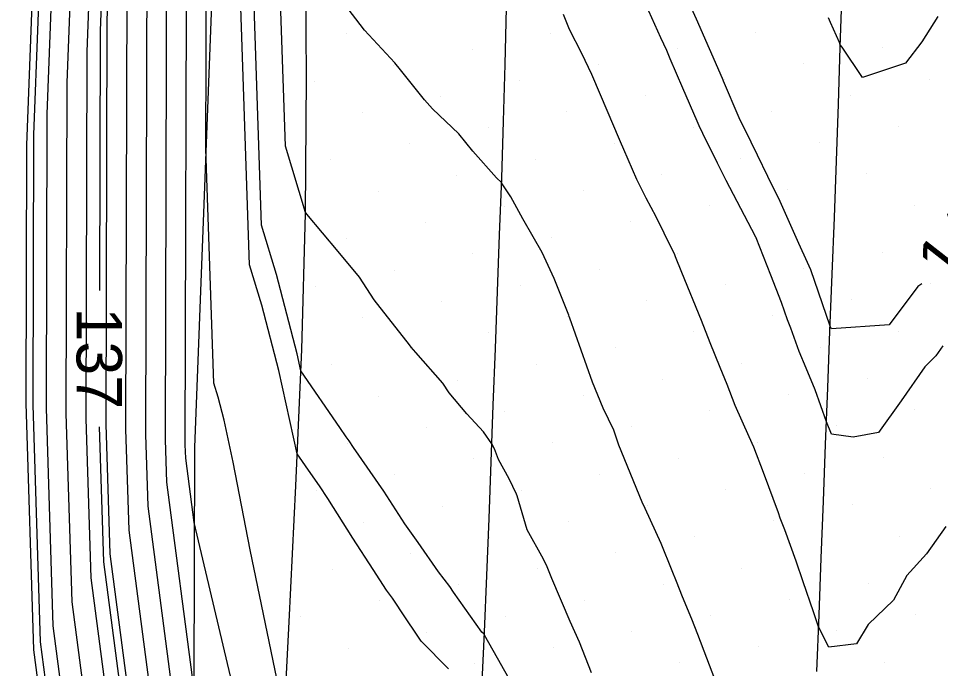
# Model space of a CAD drawing. Extents: x 2354170 to 2357230, y 866100 to 868290.
# Drawn here: x 2355317.68 to 2355358.24, y 866762.57 to 866791.19 of the extents above; entities that cross this region are included whole.
import ezdxf

# ---------------------------------------------------------------- set-up
doc = ezdxf.new("R2010")
doc.units = 0
for name, color, linetype in [('Default', 7, 'Continuous'), ('DTM Contours Major', 7, 'Continuous'), ('DTM Contours Minor', 7, 'Continuous'), ('DTM Contours Minor Text', 7, 'Continuous'), ('Exist DTM Breakline', 7, 'Continuous'), ('Exist DTM Scan Elevation Point', 7, 'Continuous'), ('Exist Roads EOP', 7, 'Continuous'), ('PH Exist DTM Breakline', 7, 'Continuous')]:
    doc.layers.add(name, color=color, linetype=linetype)

msp = doc.modelspace()

# ---------------------------------------------------------------- linework, layer by layer
at = {"layer": 'Default'}
for points in [[(2355319.839, 866834.891), (2355319.852, 866834.326), (2355319.913, 866832.709), (2355319.915, 866832.669), (2355320.627, 866818.532), (2355321.726, 866802.686), (2355321.904, 866800.122), (2355321.563, 866791.1), (2355321.517, 866773.337), (2355321.694, 866767.616), (2355323.737, 866752.092), (2355322.982, 866741.477), (2355322.473, 866736.715), (2355322.653, 866735.162)], [(2355319.531, 866703.142), (2355319.421, 866706.742), (2355319.627, 866715.191), (2355319.642, 866715.296), (2355317.686, 866732.184), (2355319.197, 866746.316), (2355319.69, 866753.255), (2355318.354, 866763.403), (2355318.019, 866774.259), (2355318.049, 866785.607), (2355318.635, 866801.132), (2355318.526, 866802.706), (2355318.518, 866802.818)], [(2355319.453, 866800.879), (2355318.927, 866786.98), (2355318.894, 866774.029), (2355319.189, 866764.456), (2355320.702, 866752.964), (2355320.143, 866745.106), (2355318.882, 866733.317), (2355321.17, 866713.572)], [(2355320.27, 866800.627), (2355319.806, 866788.354), (2355319.768, 866773.798), (2355320.024, 866765.509), (2355321.713, 866752.673), (2355321.089, 866743.896), (2355320.079, 866734.449), (2355322.698, 866711.847)], [(2355321.087, 866800.374), (2355320.685, 866789.727), (2355320.642, 866773.568), (2355320.859, 866766.563), (2355322.725, 866752.382), (2355322.036, 866742.687), (2355321.276, 866735.582), (2355323.508, 866716.313)], [(2355329.376, 866760.508), (2355327.865, 866767.792), (2355327.128, 866771.661), (2355326.722, 866773.501), (2355326.461, 866774.513), (2355326.27, 866775.141), (2355325.924, 866785.443), (2355325.957, 866797.966)], [(2355328.275, 866756.834), (2355325.406, 866768.995), (2355325.033, 866771.829), (2355325.015, 866772.415), (2355325.078, 866796.593)], [(2355336.586, 866762.561), (2355335.385, 866763.78), (2355335.183, 866764.08), (2355334.7, 866764.799), (2355334.129, 866765.669), (2355333.867, 866766.018), (2355333.28, 866766.93), (2355332.387, 866768.311), (2355331.283, 866770.057), (2355330.915, 866770.617), (2355330.533, 866771.155), (2355329.94, 866772.019), (2355329.131, 866775.693), (2355328.387, 866778.567), (2355327.846, 866780.351), (2355327.304, 866796.482)], [(2355325.388, 866761.737), (2355324.198, 866770.776), (2355324.14, 866772.646), (2355324.199, 866795.22)], [(2355323.321, 866793.847), (2355323.266, 866772.876), (2355323.363, 866769.722), (2355325.369, 866754.479), (2355325.841, 866752.48), (2355325.898, 866751.775), (2355325.98, 866750.685), (2355324.941, 866739.991), (2355324.875, 866739.057), (2355324.866, 866738.98), (2355324.891, 866738.771), (2355325.06, 866737.82), (2355327.395, 866727.737), (2355327.467, 866727.872), (2355328.608, 866726.353), (2355329.081, 866725.537), (2355330.039, 866723.985), (2355331.124, 866722.2)], [(2355357.408, 866779.505), (2355357.232, 866779.394), (2355355.983, 866777.697), (2355353.441, 866777.532), (2355353.379, 866777.638), (2355352.535, 866780.118), (2355352.389, 866780.447), (2355352.005, 866781.286), (2355351.185, 866783.131), (2355350.633, 866784.234), (2355350.187, 866785.176), (2355349.913, 866785.74), (2355349.374, 866786.814), (2355348.694, 866788.427), (2355348.673, 866788.476), (2355348.642, 866788.549), (2355347.5, 866791.154), (2355346.762, 866792.79)], [(2355322.442, 866792.473), (2355322.391, 866773.107), (2355322.528, 866768.669), (2355324.748, 866751.801), (2355323.928, 866740.267), (2355323.67, 866737.848), (2355324.43, 866731.285), (2355326.327, 866720.655)], [(2355348.472, 866761.682), (2355347.565, 866764.066), (2355347.299, 866764.743), (2355346.88, 866765.734), (2355346.616, 866766.408), (2355346.425, 866766.874), (2355345.942, 866768.075), (2355345.244, 866769.62), (2355345.117, 866769.897), (2355344.091, 866772.408), (2355343.872, 866773.065), (2355343.401, 866774.03), (2355342.928, 866775.182), (2355341.928, 866778.003), (2355341.898, 866778.075), (2355341.88, 866778.128), (2355341.245, 866779.747), (2355340.707, 866780.887), (2355340.321, 866781.576), (2355339.863, 866782.366), (2355339.332, 866783.339), (2355338.958, 866783.913), (2355338.929, 866783.962), (2355338.71, 866784.177), (2355337.664, 866785.349), (2355337.05, 866786.108), (2355335.895, 866787.206), (2355335.533, 866787.603), (2355334.481, 866788.925), (2355334.236, 866789.229), (2355332.895, 866790.674), (2355332.522, 866791.169), (2355331.742, 866792.195)], [(2355342.884, 866762.382), (2355342.359, 866763.737), (2355341.95, 866764.642), (2355341.134, 866766.537), (2355340.929, 866767.054), (2355340.773, 866767.394), (2355340.047, 866768.678), (2355339.615, 866770.173), (2355339.588, 866770.254), (2355339.261, 866770.922), (2355338.794, 866771.773), (2355338.624, 866772.238), (2355338.498, 866772.468), (2355338.134, 866773), (2355337.405, 866773.784), (2355336.621, 866774.711), (2355336.338, 866775.139), (2355335.156, 866776.488), (2355334.953, 866776.721), (2355334.873, 866776.823), (2355333.329, 866778.797), (2355332.676, 866779.805), (2355331.745, 866780.934), (2355330.36, 866782.577), (2355330.329, 866782.617), (2355330.317, 866782.631), (2355330.307, 866782.641), (2355329.422, 866785.562), (2355329.222, 866791.515)], [(2355358.474, 866768.823), (2355357.615, 866767.624), (2355356.751, 866766.668), (2355356.168, 866765.583), (2355355.047, 866764.517), (2355354.544, 866763.66), (2355353.319, 866763.517), (2355352.873, 866764.411), (2355352.727, 866764.851), (2355352.645, 866765.069), (2355352.187, 866766.395), (2355351.886, 866767.298), (2355351.388, 866768.686), (2355351.187, 866769.199), (2355351.115, 866769.433), (2355350.451, 866771.198), (2355350.022, 866772.311), (2355349.824, 866772.779), (2355349.208, 866774.152), (2355348.855, 866775.078), (2355348.537, 866775.819), (2355348.101, 866776.916), (2355347.718, 866777.891), (2355346.853, 866780.005), (2355346.575, 866780.693), (2355346.532, 866780.823), (2355346.435, 866781.016), (2355345.721, 866782.462), (2355345.289, 866783.281), (2355344.877, 866784.094), (2355344.301, 866785.426), (2355344.159, 866785.752), (2355344.065, 866785.962), (2355343.617, 866787.035), (2355342.891, 866788.718), (2355342.456, 866789.643), (2355341.914, 866790.707), (2355341.648, 866791.37)], [(2355358.116, 866791.273), (2355357.413, 866790.165), (2355356.69, 866789.219), (2355354.798, 866788.593), (2355353.915, 866789.921), (2355353.828, 866790.031), (2355353.787, 866790.127), (2355353.401, 866791.012), (2355353.304, 866791.223)]]:
    msp.add_lwpolyline(points, dxfattribs=at)
at = {"layer": 'DTM Contours Major'}
msp.add_lwpolyline([(2355358.334, 866776.78), (2355358.027, 866776.344), (2355357.548, 866775.85), (2355356.507, 866774.352), (2355355.504, 866772.962), (2355354.392, 866772.754), (2355353.436, 866772.89), (2355353.215, 866773.435), (2355352.723, 866774.836), (2355352.329, 866775.799), (2355352.019, 866776.528), (2355351.654, 866777.563), (2355351.507, 866777.921), (2355351.243, 866778.687), (2355350.772, 866779.883), (2355350.128, 866781.533), (2355350.118, 866781.554), (2355350.099, 866781.589), (2355348.804, 866784.063), (2355348.419, 866784.816), (2355347.785, 866786.118), (2355347.615, 866786.456), (2355347.527, 866786.664), (2355346.907, 866788.116), (2355346.348, 866789.413), (2355346.204, 866789.777), (2355345.939, 866790.337), (2355345.138, 866792.114)], dxfattribs=at)
at = {"layer": 'DTM Contours Minor'}
for points in [[(2355315.242, 866979.053), (2355315.645, 866971.554), (2355315.647, 866971.365), (2355315.697, 866970.436), (2355315.938, 866949.586), (2355316.345, 866939.655), (2355316.229, 866921.7), (2355316.288, 866920.303), (2355316.905, 866909.69), (2355317.696, 866891.211), (2355317.712, 866890.948), (2355317.95, 866878.41), (2355318.776, 866863.441), (2355318.797, 866862.168), (2355319.282, 866848.671), (2355319.596, 866834.276), (2355319.655, 866832.712), (2355319.657, 866832.671), (2355320.396, 866818.024), (2355321.46, 866802.688), (2355321.632, 866800.206), (2355321.27, 866790.642), (2355321.241, 866779.218)], [(2355314.895, 866894.262), (2355315.108, 866889.287), (2355315.119, 866889.115), (2355315.275, 866880.887), (2355316.318, 866861.986), (2355316.331, 866861.214), (2355316.625, 866853.034), (2355317.045, 866833.773), (2355317.084, 866832.738), (2355317.087, 866832.683), (2355318.083, 866812.944), (2355318.793, 866802.704), (2355318.908, 866801.047), (2355318.342, 866786.065), (2355318.311, 866774.182), (2355318.633, 866763.754), (2355320.027, 866753.158), (2355319.512, 866745.912), (2355318.085, 866732.561), (2355320.151, 866714.721), (2355320.138, 866714.631), (2355319.962, 866707.392), (2355320.351, 866694.691)], [(2355325.388, 866761.737), (2355324.198, 866770.776), (2355324.14, 866772.646), (2355324.199, 866795.22)], [(2355339.638, 866761.441), (2355338.172, 866764.043), (2355338.152, 866764.096), (2355338.066, 866764.177), (2355336.81, 866765.934), (2355336.647, 866766.182), (2355336.16, 866766.831), (2355335.256, 866768.116), (2355334.673, 866768.947), (2355333.756, 866770.38), (2355332.42, 866772.302), (2355332.22, 866772.59), (2355332.089, 866772.775), (2355331.811, 866773.177), (2355330.099, 866775.671), (2355329.933, 866776.424), (2355329.029, 866779.919), (2355328.372, 866782.088), (2355327.943, 866794.826)], [(2355321.231, 866773.218), (2355321.415, 866767.265), (2355323.399, 866752.188), (2355322.667, 866741.88), (2355322.074, 866736.337), (2355323.816, 866721.304)]]:
    msp.add_lwpolyline(points, dxfattribs=at)
at = {"layer": 'Exist DTM Breakline'}
for points in [[(2355352.791, 866762.441), (2355352.895, 866764.939), (2355352.989, 866767.437), (2355353.083, 866769.936), (2355353.177, 866772.434), (2355353.272, 866774.932), (2355353.371, 866777.43), (2355353.471, 866779.928), (2355353.57, 866782.426), (2355353.667, 866784.924), (2355353.746, 866787.423), (2355353.825, 866789.922), (2355353.903, 866792.42)], [(2355338.065, 866761.68), (2355338.178, 866764.177), (2355338.282, 866766.675), (2355338.375, 866769.173), (2355338.468, 866771.671), (2355338.562, 866774.17), (2355338.655, 866776.668), (2355338.749, 866779.166), (2355338.843, 866781.664), (2355338.937, 866784.163), (2355339.016, 866786.661), (2355339.079, 866789.16), (2355339.143, 866791.66)]]:
    msp.add_lwpolyline(points, dxfattribs=at)
at = {"layer": 'Exist DTM Scan Elevation Point'}
for p, q in [((2355332.086, 866790.509), (2355332.086, 866790.509)), ((2355341.099, 866790.541), (2355341.099, 866790.541)), ((2355350.113, 866790.573), (2355350.113, 866790.573)), ((2355355.663, 866789.899), (2355355.663, 866789.899)), ((2355337.635, 866789.836), (2355337.635, 866789.836)), ((2355346.649, 866789.867), (2355346.649, 866789.867)), ((2355334.171, 866789.13), (2355334.171, 866789.13)), ((2355343.184, 866789.162), (2355343.184, 866789.162)), ((2355352.198, 866789.193), (2355352.198, 866789.193)), ((2355330.706, 866788.424), (2355330.706, 866788.424)), ((2355339.72, 866788.456), (2355339.72, 866788.456)), ((2355348.734, 866788.488), (2355348.734, 866788.488)), ((2355357.748, 866788.52), (2355357.748, 866788.52)), ((2355336.256, 866787.751), (2355336.256, 866787.751)), ((2355345.269, 866787.782), (2355345.269, 866787.782)), ((2355354.283, 866787.814), (2355354.283, 866787.814)), ((2355341.805, 866787.077), (2355341.805, 866787.077)), ((2355350.819, 866787.108), (2355350.819, 866787.108)), ((2355332.791, 866787.045), (2355332.791, 866787.045)), ((2355338.34, 866786.371), (2355338.34, 866786.371)), ((2355347.354, 866786.403), (2355347.354, 866786.403)), ((2355356.368, 866786.435), (2355356.368, 866786.435)), ((2355334.876, 866785.666), (2355334.876, 866785.666)), ((2355343.89, 866785.697), (2355343.89, 866785.697)), ((2355352.904, 866785.729), (2355352.904, 866785.729)), ((2355349.439, 866785.023), (2355349.439, 866785.023)), ((2355331.412, 866784.96), (2355331.412, 866784.96)), ((2355340.425, 866784.992), (2355340.425, 866784.992)), ((2355336.961, 866784.286), (2355336.961, 866784.286)), ((2355345.975, 866784.318), (2355345.975, 866784.318)), ((2355354.989, 866784.35), (2355354.989, 866784.35)), ((2355333.497, 866783.581), (2355333.497, 866783.581)), ((2355342.51, 866783.612), (2355342.51, 866783.612)), ((2355351.524, 866783.644), (2355351.524, 866783.644)), ((2355339.046, 866782.907), (2355339.046, 866782.907)), ((2355348.06, 866782.938), (2355348.06, 866782.938)), ((2355357.074, 866782.97), (2355357.074, 866782.97)), ((2355335.582, 866782.201), (2355335.582, 866782.201)), ((2355344.595, 866782.233), (2355344.595, 866782.233)), ((2355332.117, 866781.496), (2355332.117, 866781.496)), ((2355341.131, 866781.527), (2355341.131, 866781.527)), ((2355350.145, 866781.559), (2355350.145, 866781.559)), ((2355337.667, 866780.822), (2355337.667, 866780.822)), ((2355346.68, 866780.853), (2355346.68, 866780.853)), ((2355355.694, 866780.885), (2355355.694, 866780.885)), ((2355352.23, 866780.18), (2355352.23, 866780.18)), ((2355334.202, 866780.116), (2355334.202, 866780.116)), ((2355343.216, 866780.148), (2355343.216, 866780.148)), ((2355330.738, 866779.411), (2355330.738, 866779.411)), ((2355339.752, 866779.442), (2355339.752, 866779.442)), ((2355348.765, 866779.474), (2355348.765, 866779.474)), ((2355357.779, 866779.506), (2355357.779, 866779.506)), ((2355336.287, 866778.737), (2355336.287, 866778.737)), ((2355345.301, 866778.768), (2355345.301, 866778.768)), ((2355354.315, 866778.8), (2355354.315, 866778.8)), ((2355332.823, 866778.031), (2355332.823, 866778.031)), ((2355341.837, 866778.063), (2355341.837, 866778.063)), ((2355350.85, 866778.095), (2355350.85, 866778.095)), ((2355338.372, 866777.357), (2355338.372, 866777.357)), ((2355347.386, 866777.389), (2355347.386, 866777.389)), ((2355356.4, 866777.421), (2355356.4, 866777.421)), ((2355334.908, 866776.652), (2355334.908, 866776.652)), ((2355343.922, 866776.683), (2355343.922, 866776.683)), ((2355352.935, 866776.715), (2355352.935, 866776.715)), ((2355331.443, 866775.946), (2355331.443, 866775.946)), ((2355340.457, 866775.978), (2355340.457, 866775.978)), ((2355349.471, 866776.01), (2355349.471, 866776.01)), ((2355346.007, 866775.304), (2355346.007, 866775.304)), ((2355355.02, 866775.336), (2355355.02, 866775.336)), ((2355336.993, 866775.272), (2355336.993, 866775.272)), ((2355333.528, 866774.567), (2355333.528, 866774.567)), ((2355342.542, 866774.598), (2355342.542, 866774.598)), ((2355351.556, 866774.63), (2355351.556, 866774.63)), ((2355339.078, 866773.893), (2355339.078, 866773.893)), ((2355348.092, 866773.925), (2355348.092, 866773.925)), ((2355357.105, 866773.956), (2355357.105, 866773.956)), ((2355335.613, 866773.187), (2355335.613, 866773.187)), ((2355344.627, 866773.219), (2355344.627, 866773.219)), ((2355353.641, 866773.251), (2355353.641, 866773.251)), ((2355332.149, 866772.482), (2355332.149, 866772.482)), ((2355341.163, 866772.514), (2355341.163, 866772.514)), ((2355350.177, 866772.545), (2355350.177, 866772.545)), ((2355337.698, 866771.808), (2355337.698, 866771.808)), ((2355346.712, 866771.84), (2355346.712, 866771.84)), ((2355355.726, 866771.871), (2355355.726, 866771.871)), ((2355334.234, 866771.102), (2355334.234, 866771.102)), ((2355343.248, 866771.134), (2355343.248, 866771.134)), ((2355352.262, 866771.166), (2355352.262, 866771.166)), ((2355339.783, 866770.429), (2355339.783, 866770.429)), ((2355348.797, 866770.46), (2355348.797, 866770.46)), ((2355357.811, 866770.492), (2355357.811, 866770.492)), ((2355330.769, 866770.397), (2355330.769, 866770.397)), ((2355336.319, 866769.723), (2355336.319, 866769.723)), ((2355345.333, 866769.755), (2355345.333, 866769.755)), ((2355354.347, 866769.786), (2355354.347, 866769.786)), ((2355332.854, 866769.017), (2355332.854, 866769.017)), ((2355341.868, 866769.049), (2355341.868, 866769.049)), ((2355350.882, 866769.081), (2355350.882, 866769.081)), ((2355356.432, 866768.407), (2355356.432, 866768.407)), ((2355338.404, 866768.344), (2355338.404, 866768.344)), ((2355347.418, 866768.375), (2355347.418, 866768.375)), ((2355334.939, 866767.638), (2355334.939, 866767.638)), ((2355343.953, 866767.67), (2355343.953, 866767.67)), ((2355331.475, 866766.932), (2355331.475, 866766.932)), ((2355340.489, 866766.964), (2355340.489, 866766.964)), ((2355349.503, 866766.996), (2355349.503, 866766.996)), ((2355337.024, 866766.259), (2355337.024, 866766.259)), ((2355346.038, 866766.29), (2355346.038, 866766.29)), ((2355355.052, 866766.322), (2355355.052, 866766.322)), ((2355333.56, 866765.553), (2355333.56, 866765.553)), ((2355342.574, 866765.585), (2355342.574, 866765.585)), ((2355351.588, 866765.616), (2355351.588, 866765.616)), ((2355330.096, 866764.847), (2355330.096, 866764.847)), ((2355339.109, 866764.879), (2355339.109, 866764.879)), ((2355348.123, 866764.911), (2355348.123, 866764.911)), ((2355357.137, 866764.942), (2355357.137, 866764.942)), ((2355335.645, 866764.174), (2355335.645, 866764.174)), ((2355344.659, 866764.205), (2355344.659, 866764.205)), ((2355353.673, 866764.237), (2355353.673, 866764.237)), ((2355350.208, 866763.531), (2355350.208, 866763.531)), ((2355332.181, 866763.468), (2355332.181, 866763.468)), ((2355341.194, 866763.5), (2355341.194, 866763.5)), ((2355337.73, 866762.794), (2355337.73, 866762.794)), ((2355346.744, 866762.826), (2355346.744, 866762.826)), ((2355355.758, 866762.857), (2355355.758, 866762.857))]:
    msp.add_line(p, q, dxfattribs=at)
at = {"layer": 'Exist Roads EOP'}
msp.add_lwpolyline([(2355327.012, 866722.706), (2355327.468, 866728.688), (2355327.888, 866734.674), (2355328.276, 866740.661), (2355328.634, 866746.65), (2355328.968, 866752.641), (2355329.281, 866758.633), (2355329.583, 866764.625), (2355329.879, 866770.618), (2355330.14, 866776.612), (2355330.307, 866782.61), (2355330.344, 866788.61), (2355330.303, 866794.61)], dxfattribs=at)
at = {"layer": 'PH Exist DTM Breakline'}
msp.add_lwpolyline([(2355330.739, 867042.516), (2355330.409, 867021.456), (2355330.077, 866992.331), (2355329.715, 866959.271), (2355329.332, 866929.644), (2355329.051, 866898.962), (2355328.035, 866865.741), (2355327.05, 866832.635), (2355326.439, 866798.721), (2355325.414, 866772.31), (2355325.362, 866751.624)], dxfattribs=at)

# ---------------------------------------------------------------- texts
at = {"layer": 'Default'}
msp.add_text('140', height=2, rotation=51.9984, dxfattribs=at).set_placement((2355358.626, 866779.453))
at = {"layer": 'DTM Contours Minor Text'}
msp.add_text('137', height=2, rotation=269.9131, dxfattribs=at).set_placement((2355320.236, 866778.464))

doc.saveas('drawing.dxf')
